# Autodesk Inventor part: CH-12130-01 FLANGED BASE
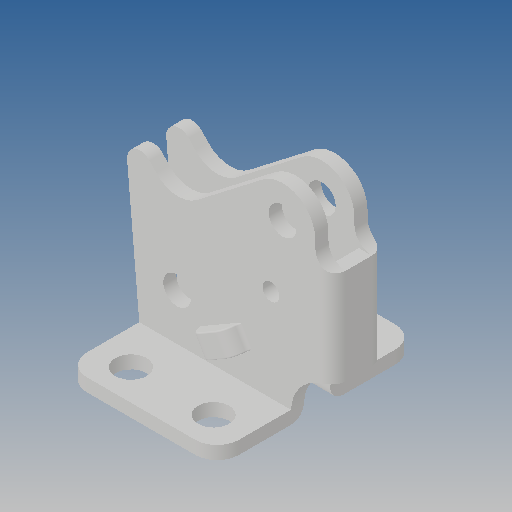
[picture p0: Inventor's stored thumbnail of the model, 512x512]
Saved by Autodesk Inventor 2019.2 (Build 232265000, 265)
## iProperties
Created: 2012-09
Part Number: CH-12130-01 FLANGED BASE
Material: Ogólny
Document SubType Name: Modeling
Designer: CADENGINEERING4
Density: 1 g/cm^3
Appearance: Domyślna
Author: CADENGINEERING4
Revision Number: ÈÎºÎ
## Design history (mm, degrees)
feature "Ô²½Ç11"
node "Bryła1"
